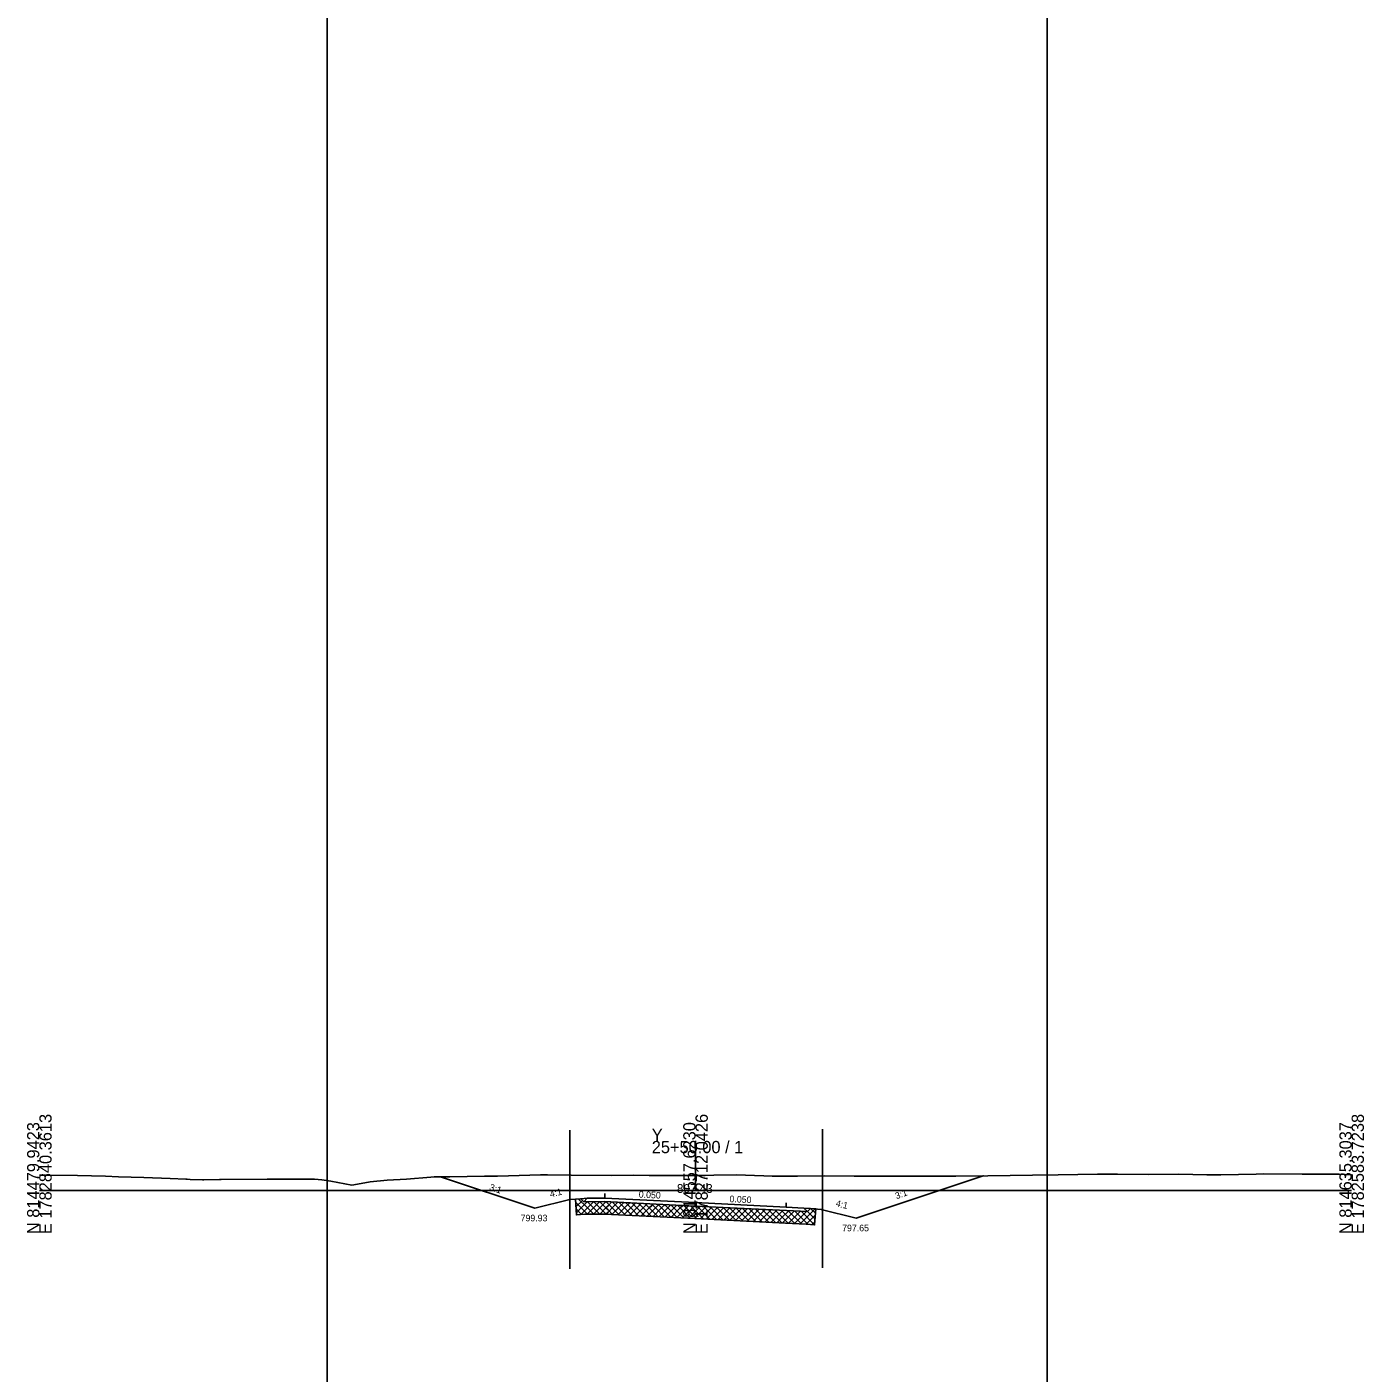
# Model space of a CAD drawing. Extents: x -12583 to 5303, y -44 to 25667.
# Drawn here: x 997.2 to 1302.8, y 5958.2 to 6266 of the extents above; entities that cross this region are included whole.
import ezdxf

# ---------------------------------------------------------------- set-up
doc = ezdxf.new("R2010")
doc.units = 0
for name, color, linetype in [('Exist Cross Section Cell', 7, 'Continuous'), ('Exist XS Center Line Elevation Label', 7, 'Continuous'), ('Exist XS Ground Line', 7, 'Continuous'), ('Prop XS Ditch Slope Text', 7, 'Continuous'), ('Prop XS Ditch Standard Text', 7, 'Continuous'), ('Prop XS Dump Level', 7, 'Continuous'), ('Prop XS Earthwork Shape', 7, 'Continuous'), ('Prop XS Earthwork Undercut', 7, 'Continuous'), ('Prop XS EOT Tick Mark', 7, 'Continuous'), ('Prop XS Exc Vertical Line 1', 7, 'Continuous'), ('Prop XS Exc Vertical Line 2', 7, 'Continuous'), ('Prop XS Finish Grade', 7, 'Continuous'), ('Prop XS Finish Grade Earthwork', 7, 'Continuous'), ('Prop XS Finish Grade Paved Shoulder', 7, 'Continuous'), ('Prop XS Finish Grade Pavement', 7, 'Continuous'), ('Prop XS Pvmt Edge Slope', 7, 'Continuous'), ('Prop XS SE Text', 7, 'Continuous'), ('Prop XS Side Slope Text', 7, 'Continuous'), ('Prop XS Subgrade Earthwork', 7, 'Continuous'), ('Prop XS Undercut Exc Hatch', 7, 'Continuous'), ('Scratch_Level_1', 7, 'Continuous'), ('Scratch_Level_2', 7, 'Continuous'), ('Scratch_Level_3', 7, 'Continuous'), ('Scratch_Level_6', 7, 'Continuous')]:
    doc.layers.add(name, color=color, linetype=linetype)

msp = doc.modelspace()

# ---------------------------------------------------------------- linework, layer by layer
at = {"layer": 'Exist Cross Section Cell'}
for p, q in [((1150, 6000), (1150, 6011.3)), ((1000, 6000), (1150, 6000)), ((1150, 6000), (1300, 6000))]:
    msp.add_line(p, q, dxfattribs=at)
at = {"layer": 'Exist XS Ground Line'}
for p, q in [((1232.94, 6003.56), (1241.9, 6003.7)), ((1241.9, 6003.7), (1246.45, 6003.72)), ((1246.45, 6003.72), (1253.52, 6003.63)), ((1253.52, 6003.63), (1260.5, 6003.7)), ((1260.5, 6003.7), (1266.93, 6003.59)), ((1270.12, 6003.57), (1278.18, 6003.72)), ((1278.18, 6003.72), (1279.95, 6003.77)), ((1279.95, 6003.77), (1288.68, 6003.68)), ((1288.68, 6003.68), (1297.18, 6003.67)), ((1297.18, 6003.67), (1300, 6003.58)), ((1000, 6003.49), (1001.42, 6003.48)), ((1001.42, 6003.48), (1008.74, 6003.39)), ((1008.74, 6003.39), (1015.11, 6003.23)), ((1015.11, 6003.23), (1018.1, 6003.13)), ((1018.1, 6003.13), (1023.89, 6002.92)), ((1023.89, 6002.92), (1029.9, 6002.71)), ((1029.9, 6002.71), (1033.48, 6002.55)), ((1033.48, 6002.55), (1033.79, 6002.53)), ((1033.79, 6002.53), (1034.48, 6002.51)), ((1034.48, 6002.51), (1037.27, 6002.39)), ((1037.27, 6002.39), (1037.63, 6002.38)), ((1037.63, 6002.38), (1041.15, 6002.49)), ((1041.15, 6002.49), (1041.59, 6002.49)), ((1041.59, 6002.49), (1052.1, 6002.58)), ((1052.1, 6002.58), (1054.21, 6002.59)), ((1054.21, 6002.59), (1062.91, 6002.57)), ((1062.91, 6002.57), (1064.55, 6002.4)), ((1064.55, 6002.4), (1066.64, 6002.11)), ((1066.64, 6002.11), (1069.8, 6001.52)), ((1069.8, 6001.52), (1071.46, 6001.19)), ((1071.46, 6001.19), (1073.58, 6001.59)), ((1073.58, 6001.59), (1075.59, 6001.99)), ((1075.59, 6001.99), (1079.49, 6002.34)), ((1079.49, 6002.34), (1083.93, 6002.58)), ((1083.93, 6002.58), (1089.46, 6003.03)), ((1089.46, 6003.03), (1090.27, 6003.08)), ((1090.27, 6003.08), (1090.81, 6003.1)), ((1090.81, 6003.1), (1093.86, 6003.13)), ((1093.86, 6003.13), (1101.73, 6003.21)), ((1101.73, 6003.21), (1104.73, 6003.28)), ((1104.73, 6003.28), (1107.23, 6003.34)), ((1107.23, 6003.34), (1114.6, 6003.54)), ((1114.6, 6003.54), (1116.16, 6003.53)), ((1116.16, 6003.53), (1121.61, 6003.45)), ((1121.61, 6003.45), (1130.84, 6003.42)), ((1130.84, 6003.42), (1135.75, 6003.45)), ((1135.75, 6003.45), (1139.37, 6003.43)), ((1139.37, 6003.43), (1145.25, 6003.43)), ((1145.25, 6003.43), (1150, 6003.43)), ((1150, 6003.43), (1152.24, 6003.43)), ((1152.24, 6003.43), (1154.18, 6003.44)), ((1154.18, 6003.44), (1159.26, 6003.54)), ((1159.26, 6003.54), (1165.61, 6003.29)), ((1165.61, 6003.29), (1167.5, 6003.27)), ((1167.5, 6003.27), (1173.31, 6003.24)), ((1173.31, 6003.24), (1179.46, 6003.34)), ((1179.46, 6003.34), (1186.28, 6003.26)), ((1186.28, 6003.26), (1192.82, 6003.25)), ((1192.82, 6003.25), (1200.98, 6003.27)), ((1200.98, 6003.27), (1209.51, 6003.26)), ((1209.51, 6003.26), (1216.82, 6003.34)), ((1216.82, 6003.34), (1227.04, 6003.47)), ((1227.04, 6003.47), (1232.94, 6003.56)), ((1266.93, 6003.59), (1270.12, 6003.57))]:
    msp.add_line(p, q, dxfattribs=at)
at = {"layer": 'Prop XS Dump Level'}
for p, q in [((1129.25, 5998.25), (1150, 5997.21)), ((1150, 5997.21), (1170.75, 5996.17))]:
    msp.add_line(p, q, dxfattribs=at)
at = {"layer": 'Prop XS Earthwork Shape'}
msp.add_lwpolyline([(1091.71, 6003.11), (1093.86, 6003.13), (1101.73, 6003.21), (1104.73, 6003.28), (1107.23, 6003.34), (1114.6, 6003.54), (1116.16, 6003.53), (1121.61, 6003.45), (1130.84, 6003.42), (1135.75, 6003.45), (1139.37, 6003.43), (1145.25, 6003.43), (1150, 6003.43), (1152.24, 6003.43), (1154.18, 6003.44), (1159.26, 6003.54), (1165.61, 6003.29), (1167.5, 6003.27), (1173.31, 6003.24), (1179.46, 6003.34), (1186.28, 6003.26), (1192.82, 6003.25), (1200.98, 6003.27), (1209.51, 6003.26), (1215.77, 6003.33), (1186.75, 5993.65), (1178.75, 5995.65), (1176.3, 5995.85), (1175.58, 5995.14), (1149.96, 5996.42), (1129.23, 5997.46), (1124.45, 5997.41), (1123.76, 5998.1), (1121.25, 5997.93), (1113.25, 5995.93)], close=True, dxfattribs=at)
at = {"layer": 'Prop XS Earthwork Undercut'}
for p, q in [((1122.54, 5998.02), (1122.79, 5994.4)), ((1124.7, 5994.54), (1122.79, 5994.4)), ((1129.19, 5994.58), (1124.7, 5994.54)), ((1149.85, 5993.55), (1129.19, 5994.58)), ((1177.5, 5995.75), (1177.21, 5992.12)), ((1170.6, 5992.51), (1149.85, 5993.55)), ((1170.6, 5992.51), (1175.26, 5992.28)), ((1175.26, 5992.28), (1177.21, 5992.12))]:
    msp.add_line(p, q, dxfattribs=at)
at = {"layer": 'Prop XS EOT Tick Mark'}
for p, q in [((1129.25, 5998.25), (1129.25, 5999.25)), ((1170.75, 5996.17), (1170.75, 5997.17))]:
    msp.add_line(p, q, dxfattribs=at)
at = {"layer": 'Prop XS Exc Vertical Line 1'}
msp.add_line((1121.25, 5982.07), (1121.25, 6013.73), dxfattribs=at)
at = {"layer": 'Prop XS Exc Vertical Line 2'}
msp.add_line((1179.02, 5982.3), (1179.02, 6013.96), dxfattribs=at)
at = {"layer": 'Prop XS Finish Grade'}
for p, q in [((1125.25, 5998.21), (1123.76, 5998.1)), ((1174.75, 5995.97), (1176.3, 5995.85))]:
    msp.add_line(p, q, dxfattribs=at)
at = {"layer": 'Prop XS Finish Grade Earthwork'}
for p, q in [((1113.25, 5995.93), (1091.71, 6003.11)), ((1186.75, 5993.65), (1215.77, 6003.33)), ((1121.25, 5997.93), (1113.25, 5995.93)), ((1121.25, 5997.93), (1123.76, 5998.1)), ((1176.3, 5995.85), (1178.75, 5995.65)), ((1178.75, 5995.65), (1186.75, 5993.65))]:
    msp.add_line(p, q, dxfattribs=at)
at = {"layer": 'Prop XS Finish Grade Paved Shoulder'}
for p, q in [((1129.25, 5998.25), (1125.25, 5998.21)), ((1170.75, 5996.17), (1174.75, 5995.97))]:
    msp.add_line(p, q, dxfattribs=at)
at = {"layer": 'Prop XS Finish Grade Pavement'}
for p, q in [((1129.25, 5998.25), (1150, 5997.21)), ((1150, 5997.21), (1170.75, 5996.17))]:
    msp.add_line(p, q, dxfattribs=at)
at = {"layer": 'Prop XS Pvmt Edge Slope'}
for p, q in [((1125.25, 5998.21), (1124.45, 5997.41)), ((1174.75, 5995.97), (1175.58, 5995.14))]:
    msp.add_line(p, q, dxfattribs=at)
at = {"layer": 'Prop XS Subgrade Earthwork'}
for p, q in [((1124.45, 5997.41), (1123.76, 5998.1)), ((1129.23, 5997.46), (1124.45, 5997.41)), ((1129.23, 5997.46), (1149.96, 5996.42)), ((1149.96, 5996.42), (1175.58, 5995.14)), ((1175.58, 5995.14), (1176.3, 5995.85))]:
    msp.add_line(p, q, dxfattribs=at)
at = {"layer": 'Prop XS Undercut Exc Hatch'}
for p, q in [((1122.66, 5996.2), (1124.16, 5997.7)), ((1125.28, 5996), (1123.21, 5998.07)), ((1123.86, 5996), (1122.59, 5997.27)), ((1123.96, 5994.49), (1122.7, 5995.75)), ((1122.76, 5994.88), (1123.88, 5996)), ((1123.76, 5994.47), (1125.29, 5996)), ((1125.32, 5994.54), (1123.86, 5996)), ((1123.88, 5996), (1125.29, 5997.42)), ((1125.25, 5994.54), (1126.7, 5996)), ((1126.69, 5996), (1125.27, 5997.42)), ((1126.72, 5994.56), (1125.28, 5996)), ((1125.29, 5996), (1126.72, 5997.43)), ((1128.11, 5996), (1126.67, 5997.43)), ((1126.67, 5994.56), (1128.12, 5996)), ((1128.12, 5994.57), (1126.69, 5996)), ((1126.7, 5996), (1128.15, 5997.45)), ((1129.52, 5996), (1128.07, 5997.45)), ((1128.1, 5994.57), (1129.53, 5996)), ((1129.54, 5994.56), (1128.11, 5996)), ((1128.12, 5996), (1129.56, 5997.44)), ((1130, 5996.93), (1129.49, 5997.44)), ((1129.51, 5994.57), (1130, 5995.05)), ((1130, 5995.52), (1129.52, 5996)), ((1129.53, 5996), (1130, 5996.47)), ((1130, 5996.47), (1130.91, 5997.37)), ((1130.93, 5996), (1130, 5996.93)), ((1130, 5995.05), (1130.95, 5996)), ((1131.03, 5994.49), (1130, 5995.52)), ((1130.86, 5994.5), (1132.36, 5996)), ((1132.52, 5994.42), (1130.93, 5996)), ((1130.95, 5996), (1132.25, 5997.31)), ((1132.35, 5996), (1130.98, 5997.37)), ((1132.21, 5994.43), (1133.77, 5996)), ((1134.01, 5994.34), (1132.35, 5996)), ((1132.36, 5996), (1133.6, 5997.24)), ((1133.76, 5996), (1132.47, 5997.3)), ((1133.55, 5994.36), (1135.19, 5996)), ((1135.5, 5994.27), (1133.76, 5996)), ((1133.77, 5996), (1134.95, 5997.17)), ((1135.18, 5996), (1133.96, 5997.22)), ((1134.9, 5994.3), (1136.6, 5996)), ((1136.98, 5994.19), (1135.18, 5996)), ((1135.19, 5996), (1136.29, 5997.1)), ((1136.59, 5996), (1135.44, 5997.15)), ((1136.25, 5994.23), (1138.02, 5996)), ((1138.47, 5994.12), (1136.59, 5996)), ((1136.6, 5996), (1137.64, 5997.04)), ((1138, 5996), (1136.93, 5997.07)), ((1137.59, 5994.16), (1139.43, 5996)), ((1139.96, 5994.04), (1138, 5996)), ((1138.02, 5996), (1138.99, 5996.97)), ((1139.42, 5996), (1138.42, 5997)), ((1138.94, 5994.09), (1140, 5995.15)), ((1140, 5995.42), (1139.42, 5996)), ((1139.43, 5996), (1140, 5996.57)), ((1140, 5996.83), (1139.91, 5996.92)), ((1140, 5996.57), (1140.33, 5996.9)), ((1140.83, 5996), (1140, 5996.83)), ((1140, 5995.15), (1140.85, 5996)), ((1141.45, 5993.97), (1140, 5995.42)), ((1140.29, 5994.03), (1142.26, 5996)), ((1142.94, 5993.89), (1140.83, 5996)), ((1140.85, 5996), (1141.68, 5996.83)), ((1142.25, 5996), (1141.4, 5996.85)), ((1141.63, 5993.96), (1143.67, 5996)), ((1144.43, 5993.82), (1142.25, 5996)), ((1142.26, 5996), (1143.03, 5996.77)), ((1143.66, 5996), (1142.89, 5996.77)), ((1142.98, 5993.89), (1145.09, 5996)), ((1145.92, 5993.75), (1143.66, 5996)), ((1143.67, 5996), (1144.37, 5996.7)), ((1144.33, 5993.82), (1146.5, 5996)), ((1145.08, 5996), (1144.38, 5996.7)), ((1147.41, 5993.67), (1145.08, 5996)), ((1145.09, 5996), (1145.72, 5996.63)), ((1145.67, 5993.76), (1147.92, 5996)), ((1146.49, 5996), (1145.86, 5996.63)), ((1148.89, 5993.6), (1146.49, 5996)), ((1146.5, 5996), (1147.07, 5996.57)), ((1147.02, 5993.69), (1149.33, 5996)), ((1147.9, 5996), (1147.35, 5996.55)), ((1150, 5993.9), (1147.9, 5996)), ((1147.92, 5996), (1148.42, 5996.5)), ((1148.37, 5993.62), (1150, 5995.25)), ((1149.32, 5996), (1148.84, 5996.48)), ((1150, 5995.32), (1149.32, 5996)), ((1149.33, 5996), (1149.76, 5996.43)), ((1150, 5993.84), (1152.16, 5996)), ((1150, 5995.25), (1150.75, 5996)), ((1151.87, 5993.45), (1150, 5995.32)), ((1150.73, 5996), (1150.33, 5996.4)), ((1153.36, 5993.37), (1150.73, 5996)), ((1150.75, 5996), (1151.11, 5996.36)), ((1151.06, 5993.49), (1153.57, 5996)), ((1152.15, 5996), (1151.82, 5996.33)), ((1154.85, 5993.3), (1152.15, 5996)), ((1152.16, 5996), (1152.46, 5996.3)), ((1152.41, 5993.42), (1154.99, 5996)), ((1153.56, 5996), (1153.31, 5996.25)), ((1156.34, 5993.22), (1153.56, 5996)), ((1153.57, 5996), (1153.8, 5996.23)), ((1153.76, 5993.35), (1156.4, 5996)), ((1154.98, 5996), (1154.8, 5996.18)), ((1157.83, 5993.15), (1154.98, 5996)), ((1154.99, 5996), (1155.15, 5996.16)), ((1155.1, 5993.29), (1157.82, 5996)), ((1156.39, 5996), (1156.29, 5996.1)), ((1159.31, 5993.08), (1156.39, 5996)), ((1156.4, 5996), (1156.5, 5996.09)), ((1156.45, 5993.22), (1159.19, 5995.96)), ((1157.8, 5996), (1157.77, 5996.03)), ((1160, 5993.8), (1157.8, 5996)), ((1157.8, 5993.15), (1160, 5995.36)), ((1157.82, 5996), (1157.84, 5996.03)), ((1160, 5995.22), (1159.26, 5995.96)), ((1160, 5995.36), (1160.54, 5995.89)), ((1160, 5993.94), (1161.88, 5995.82)), ((1162.29, 5992.93), (1160, 5995.22)), ((1160.49, 5993.02), (1163.23, 5995.76)), ((1163.78, 5992.85), (1160.75, 5995.88)), ((1161.84, 5992.95), (1164.58, 5995.69)), ((1165.27, 5992.78), (1162.24, 5995.81)), ((1163.18, 5992.88), (1165.92, 5995.62)), ((1166.76, 5992.7), (1163.73, 5995.73)), ((1164.53, 5992.81), (1167.27, 5995.56)), ((1168.25, 5992.63), (1165.22, 5995.66)), ((1165.88, 5992.75), (1168.62, 5995.49)), ((1169.73, 5992.55), (1166.71, 5995.58)), ((1167.22, 5992.68), (1169.96, 5995.42)), ((1170, 5993.7), (1168.19, 5995.51)), ((1170, 5995.12), (1169.68, 5995.43)), ((1170, 5994.04), (1171.31, 5995.35)), ((1170, 5992.63), (1172.66, 5995.29)), ((1172.71, 5992.41), (1170, 5995.12)), ((1174.2, 5992.33), (1171.17, 5995.36)), ((1171.26, 5992.48), (1174.01, 5995.22)), ((1172.61, 5992.41), (1175.35, 5995.15)), ((1175.7, 5992.24), (1172.66, 5995.29)), ((1173.96, 5992.34), (1177.38, 5995.76)), ((1177.21, 5992.15), (1174.15, 5995.21)), ((1177.31, 5993.46), (1175.61, 5995.16)), ((1177.42, 5994.77), (1176.32, 5995.87)), ((1149.71, 5993.56), (1150, 5993.84)), ((1150.38, 5993.52), (1150, 5993.9)), ((1159.14, 5993.08), (1160, 5993.94)), ((1160.8, 5993), (1160, 5993.8)), ((1168.57, 5992.61), (1170, 5994.04)), ((1169.92, 5992.55), (1170, 5992.63)), ((1171.22, 5992.48), (1170, 5993.7)), ((1175.3, 5992.27), (1177.38, 5994.36)), ((1176.61, 5992.17), (1177.26, 5992.82))]:
    msp.add_line(p, q, dxfattribs=at)
at = {"layer": 'Scratch_Level_1'}
msp.add_line((1065.76, 8031.12), (1065.76, -44.39), dxfattribs=at)
at = {"layer": 'Scratch_Level_2'}
msp.add_line((1230.36, 8031.12), (1230.36, -44.39), dxfattribs=at)
at = {"layer": 'Scratch_Level_3'}
msp.add_lwpolyline([(1150, 5997.21), (1170.75, 5996.17), (1174.75, 5995.97), (1176.3, 5995.85), (1175.58, 5995.14), (1149.96, 5996.42), (1129.23, 5997.46), (1124.45, 5997.41), (1123.76, 5998.1), (1125.25, 5998.21), (1129.25, 5998.25)], close=True, dxfattribs=at)
at = {"layer": 'Scratch_Level_6'}
msp.add_lwpolyline([(1122.54, 5998.02), (1123.76, 5998.1), (1124.45, 5997.41), (1129.23, 5997.46), (1149.96, 5996.42), (1175.58, 5995.14), (1176.3, 5995.85), (1177.5, 5995.75), (1177.21, 5992.12), (1175.26, 5992.28), (1170.6, 5992.51), (1149.85, 5993.55), (1129.19, 5994.58), (1124.7, 5994.54), (1122.79, 5994.4)], close=True, dxfattribs=at)

# ---------------------------------------------------------------- texts
at = {"layer": 'Exist Cross Section Cell'}
for s, p in [('E 1782840.3613', (1002.8, 5990)), ('E 1782712.0426', (1152.8, 5990)), ('E 1782583.7238', (1302.8, 5990)), ('N 814479.9423', (1000, 5990)), ('N 814557.6230', (1150, 5990)), ('N 814635.3037', (1300, 5990))]:
    msp.add_text(s, height=2.8, rotation=90, dxfattribs=at).set_placement(p)
for s, p in [('Y', (1140, 6011.3)), ('25+50.00 / 1', (1140, 6008.5))]:
    msp.add_text(s, height=2.8, dxfattribs=at).set_placement(p)
at = {"layer": 'Exist XS Center Line Elevation Label'}
msp.add_text('807.43', height=2, dxfattribs=at).set_placement((1145.75, 5999.43))
at = {"layer": 'Prop XS Ditch Slope Text'}
for rotation, p in [(14.0362, (1116.89, 5998.38)), (345.9638, (1181.94, 5996.4))]:
    msp.add_text('4:1', height=1.5, rotation=rotation, dxfattribs=at).set_placement(p)
at = {"layer": 'Prop XS Ditch Standard Text'}
for s, p in [('799.93', (1110.02, 5992.93)), ('797.65', (1183.52, 5990.65))]:
    msp.add_text(s, height=1.5, dxfattribs=at).set_placement(p)
at = {"layer": 'Prop XS Dump Level'}
for p in [(1121.25, 5997.89), (1178.75, 5995.61)]:
    msp.add_text('Case2', height=0.04, dxfattribs=at).set_placement(p)
at = {"layer": 'Prop XS SE Text'}
for p in [(1137, 5998.36), (1157.75, 5997.32)]:
    msp.add_text('0.050', height=1.5, rotation=357.1376, dxfattribs=at).set_placement(p)
at = {"layer": 'Prop XS Side Slope Text'}
for rotation, p in [(341.5651, (1102.74, 6000.12)), (20.2174, (1195.96, 5997.95))]:
    msp.add_text('3:1', height=1.5, rotation=rotation, dxfattribs=at).set_placement(p)

doc.saveas('drawing.dxf')
